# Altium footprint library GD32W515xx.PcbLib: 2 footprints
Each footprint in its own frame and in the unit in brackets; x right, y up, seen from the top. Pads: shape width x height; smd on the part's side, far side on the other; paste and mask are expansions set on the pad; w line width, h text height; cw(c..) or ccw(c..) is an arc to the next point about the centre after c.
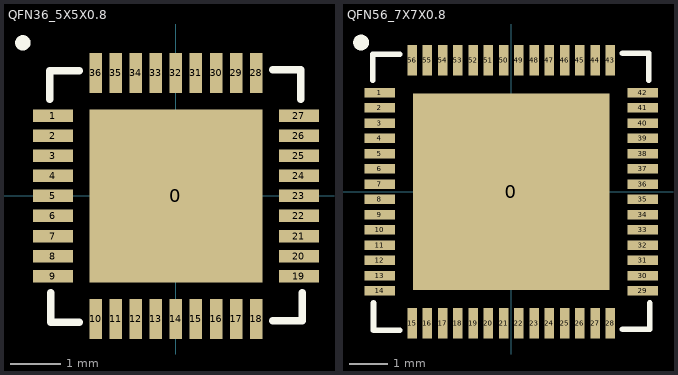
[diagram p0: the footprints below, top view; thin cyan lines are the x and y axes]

## QFN36_5X5X0.8 [mm]
pads (37):
  rect 3.45x3.45 smd: 0(0,0)
  rect 0.8x0.25 smd: 1(-2.45,1.6) 2(-2.45,1.2) 3(-2.45,0.8) 4(-2.45,0.4) 5(-2.45,0) 6(-2.45,-0.4) 7(-2.45,-0.8) 8(-2.45,-1.2) 9(-2.45,-1.6) 19(2.45,-1.6) 20(2.45,-1.2) 21(2.45,-0.8) 22(2.45,-0.4) 23(2.45,0) 24(2.45,0.4) 25(2.45,0.8) 26(2.45,1.2) 27(2.45,1.6)
  rect 0.25x0.8 smd: 10(-1.6,-2.45) 11(-1.2,-2.45) 12(-0.8,-2.45) 13(-0.4,-2.45) 14(0,-2.45) 15(0.4,-2.45) 16(0.8,-2.45) 17(1.2,-2.45) 18(1.6,-2.45) 28(1.6,2.45) 29(1.2,2.45) 30(0.8,2.45) 31(0.4,2.45) 32(0,2.45) 33(-0.4,2.45) 34(-0.8,2.45) 35(-1.2,2.45) 36(-1.6,2.45)
Top Overlay:
  circle w0.152: c-3.048,3.048 r0.076
  lines w0.152: -2.515,1.93 -2.515,2.489 -1.93,2.489 ; -2.489,-1.93 -2.489,-2.515 -1.93,-2.515 ; 1.93,-2.489 2.515,-2.489 2.515,-1.93 ; 1.93,2.515 2.489,2.515 2.489,1.93
3D body "QFN40P500X500X80_HS-37N.step": height 0.8, standoff 0, extent -2.551,-2.551 2.551,2.551

## QFN56_7X7X0.8 [mm]
pads (57):
  rect 5.15x5.15 smd: 0(0,0)
  rect 0.8x0.25 smd: 1(-3.45,2.6) 2(-3.45,2.2) 3(-3.45,1.8) 4(-3.45,1.4) 5(-3.45,1) 6(-3.45,0.6) 7(-3.45,0.2) 8(-3.45,-0.2) 9(-3.45,-0.6) 10(-3.45,-1) 11(-3.45,-1.4) 12(-3.45,-1.8) 13(-3.45,-2.2) 14(-3.45,-2.6) 29(3.45,-2.6) 30(3.45,-2.2) 31(3.45,-1.8) 32(3.45,-1.4) 33(3.45,-1) 34(3.45,-0.6) 35(3.45,-0.2) 36(3.45,0.2) 37(3.45,0.6) 38(3.45,1) 39(3.45,1.4) 40(3.45,1.8) 41(3.45,2.2) 42(3.45,2.6)
  rect 0.25x0.8 smd: 15(-2.6,-3.45) 16(-2.2,-3.45) 17(-1.8,-3.45) 18(-1.4,-3.45) 19(-1,-3.45) 20(-0.6,-3.45) 21(-0.2,-3.45) 22(0.2,-3.45) 23(0.6,-3.45) 24(1,-3.45) 25(1.4,-3.45) 26(1.8,-3.45) 27(2.2,-3.45) 28(2.6,-3.45) 43(2.6,3.45) 44(2.2,3.45) 45(1.8,3.45) 46(1.4,3.45) 47(1,3.45) 48(0.6,3.45) 49(0.2,3.45) 50(-0.2,3.45) 51(-0.6,3.45) 52(-1,3.45) 53(-1.4,3.45) 54(-1.8,3.45) 55(-2.2,3.45) 56(-2.6,3.45)
Top Overlay:
  circle w0.254: c-3.937,3.912 r0.08
  lines w0.152: -3.632,2.921 -3.632,3.607 -2.921,3.607 ; -3.607,-2.921 -3.607,-3.632 -2.921,-3.632 ; 2.921,-3.607 3.632,-3.607 3.632,-2.921 ; 2.921,3.632 3.607,3.632 3.607,2.921
3D body "QFN40P700X700X80_HS-57N.step": height 0.8, standoff 0, extent -3.551,-3.551 3.551,3.551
